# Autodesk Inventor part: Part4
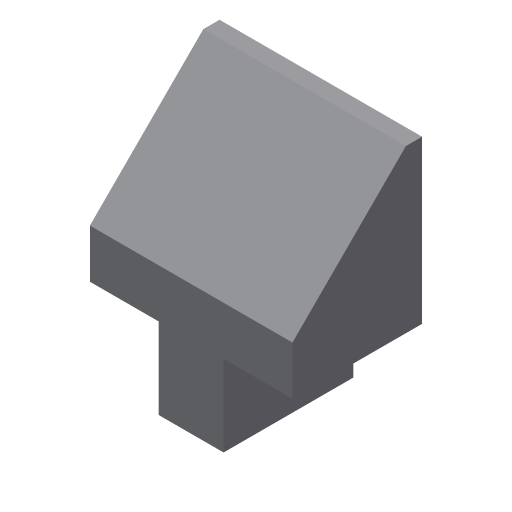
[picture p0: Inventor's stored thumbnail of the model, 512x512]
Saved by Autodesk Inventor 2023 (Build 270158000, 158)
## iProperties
Created: 2002-01
Part Number: Part4
Document SubType Name: Modeling
Designer: ***
Density: 1 g/cm^3
Material: Generic
Appearance: Default
Control State: 0
Master: False
Checked Out: False
Shininess: 77.0
Length Units: 11269
Angle Units: 11279
Time Units: 11290
Mass Units: 11283
Length Display Precision: 3
Angle Display Precision: 2
Density: 0.0
Volumn: 0.0
Area: 0.0
PropertySet Name: Model Information
Author: ***
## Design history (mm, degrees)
sketch "Sketch2"
  geometry: L1 (2.32, -6.969)-(2.32, 13.031); L2 (2.32, 13.031)-(0.32, 13.031); L3 (0.32, 13.031)-(-13.68, -0.969); L4 (-13.68, -0.969)-(-13.68, -6.969); L5 (-13.68, -6.969)-(2.32, -6.969)
  constraints: 10 end point, 2 parallel, 1 perpendicular, 1 vertical
  dimensions: "d0" = 2 distance of L1.end L2.end; "d1" = 135 deg angle of L4 L3; "d2" = 20 distance of L1.start L1.end; "d3" = 16 distance of L4.end L1.start
extrude "Extrusion1" new body sketch "Sketch2" stored distance "d4" = 25; taper "d5" = 0 deg
sketch "Sketch3"
  geometry: L1 (-13.68, -6.969)-(2.32, -6.969); L2 (2.32, -6.969)-(2.32, -16.969); L3 (2.32, -16.969)-(-13.68, -16.969); L4 (-13.68, -16.969)-(-13.68, -6.969); L5 (-13.68, -6.969)-(2.32, -6.969) reference; L6 (-13.68, -0.969)-(-13.68, -6.969) reference; L7 (2.32, -6.969)-(2.32, 13.031) reference
  constraints: 8 end point, 3 collinear, 2 parallel, 1 horizontal, 1 perpendicular
  dimensions: "d6" = 10 distance of L3.end L1.start
extrude "Extrusion2" join sketch "Sketch3" stored distance "d7" = 8; taper "d8" = 0 deg
body "Solid1"
